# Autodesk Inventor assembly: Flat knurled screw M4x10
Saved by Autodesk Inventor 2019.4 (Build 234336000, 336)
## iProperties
Created: 2021-08
Part Number: Flat knurled screw M4x10
Document SubType Name: Assembly
Designer: Administrator
Title: Flat knurled screw M4x10 v5
Author: Administrator
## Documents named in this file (2)
- c:\worker\convert-fusion-r06\tmp\job-1\20\output\files\f01db8e3-9ba6-469c-91a4-18b8ab1b818d\Flat knurled screw M4x10 v5.iam
- c:\worker\convert-fusion-r06\tmp\job-1\20\output\files\f01db8e3-9ba6-469c-91a4-18b8ab1b818d\_Flat knurled screw DIN 653-M4-10-ZB.ipt
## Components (1 placed, 1 different names)
1. _Flat knurled screw DIN 653-M4-10-ZB:1
